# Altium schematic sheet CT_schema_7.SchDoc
size 274 x 160 mm
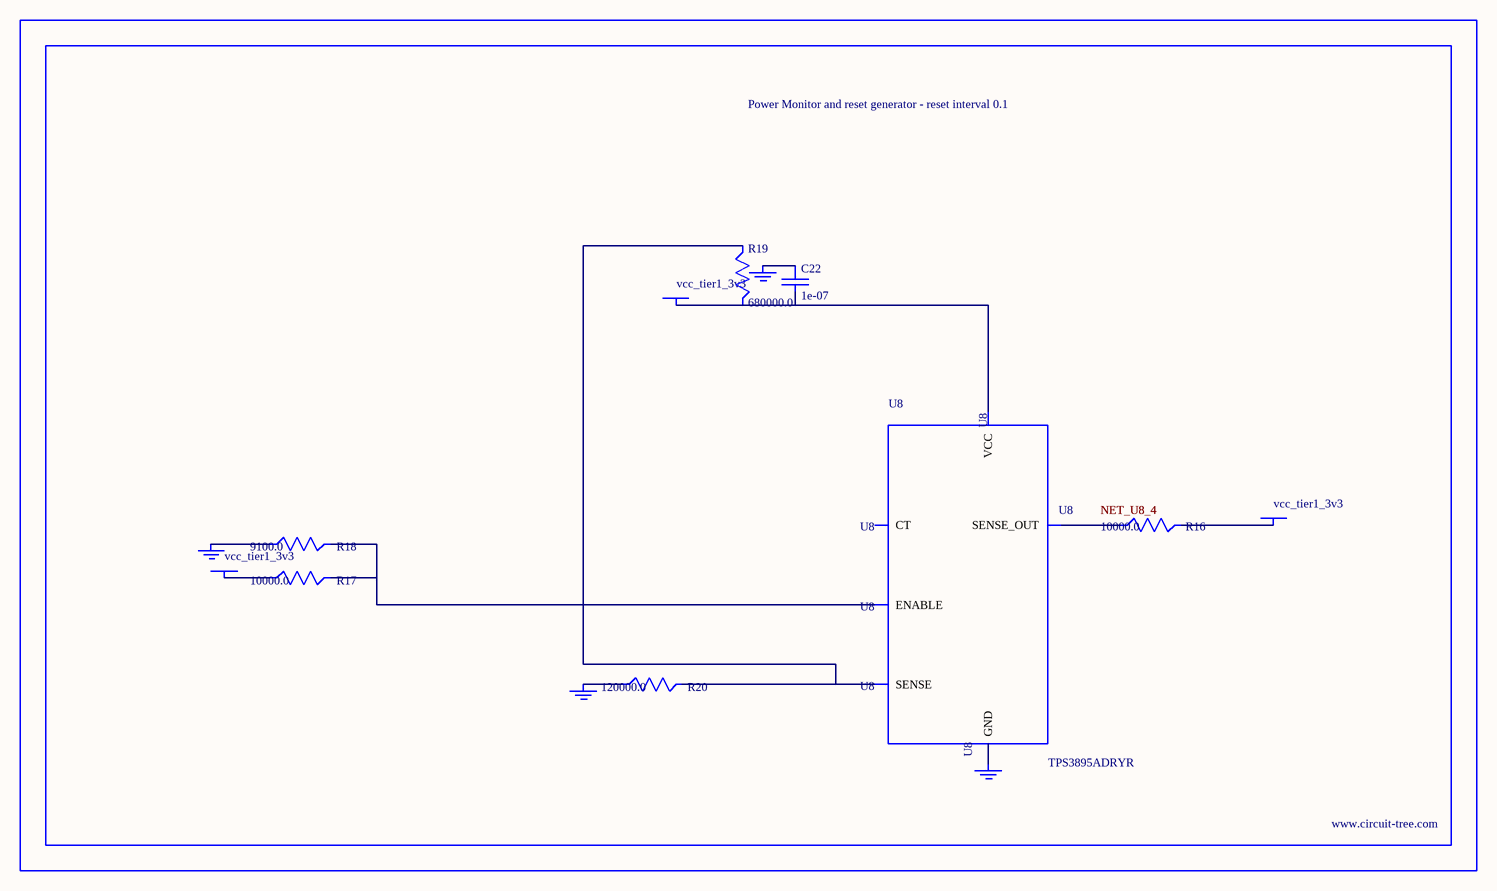
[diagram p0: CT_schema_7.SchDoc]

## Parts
BORDER6  (no value)
C22  1e-07  [C0402]
GND_INSTANCE_6_0  (no value)
GND_INSTANCE_6_1  (no value)
GND_INSTANCE_6_2  (no value)
GND_INSTANCE_6_3  (no value)
POWER_INSTANCE_6_0  vcc_tier1_3v3
POWER_INSTANCE_6_1  vcc_tier1_3v3
POWER_INSTANCE_6_2  vcc_tier1_3v3
R16  10000.0  [R0603]
R17  10000.0  [R0603]
R18  9100.0  [R0603]
R19  680000.0  [R0603]
R20  120000.0  [R0603]
U8  TPS3895ADRYR  [SON-6]

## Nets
NetC22_1: C22.1 GND_INSTANCE_6_2.0(GND)
NetC22_2: C22.2 POWER_INSTANCE_6_2.0(PWR) R19.2 U8.6(VCC)
NetGND_INSTANCE_6_0_0: GND_INSTANCE_6_0.0(GND) R18.1
NetGND_INSTANCE_6_1_0: GND_INSTANCE_6_1.0(GND) R20.1
NetGND_INSTANCE_6_3_0: GND_INSTANCE_6_3.0(GND) U8.2(GND)
NetPOWER_INSTANCE_6_0_0: POWER_INSTANCE_6_0.0(PWR) R17.1
NetPOWER_INSTANCE_6_1_0: POWER_INSTANCE_6_1.0(PWR) R16.2
NetR16_1: R16.1 U8.4(SENSE_OUT)
NetR17_2: R17.2 R18.2 U8.1(ENABLE)
NetR19_1: R19.1 R20.2 U8.3(SENSE)

Not connected (* = marked no-connect by the designer): U8 5(CT)

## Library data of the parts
BORDER6 = BORDER_PAGE6
C22 = C0402C104K3RACTU
GND_INSTANCE_6_0-GND_INSTANCE_6_3 = GND
POWER_INSTANCE_6_0-POWER_INSTANCE_6_2 = PWR
R16 R17 = RC0603JR-0710KL
R18 = RC0603JR-079K1L
R19 = RC0603JR-07680KL
R20 = RC0603JR-07120KL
